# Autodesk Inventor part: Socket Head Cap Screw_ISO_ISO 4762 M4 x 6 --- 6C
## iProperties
Created: 2011-02
Part Number: Socket Head Cap Screw_ISO_ISO 4762 M4 x 6 --- 6C
Document SubType Name: Modeling
Designer: eric
Density: 1 g/cm^3
Author: eric
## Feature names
1. Base1
